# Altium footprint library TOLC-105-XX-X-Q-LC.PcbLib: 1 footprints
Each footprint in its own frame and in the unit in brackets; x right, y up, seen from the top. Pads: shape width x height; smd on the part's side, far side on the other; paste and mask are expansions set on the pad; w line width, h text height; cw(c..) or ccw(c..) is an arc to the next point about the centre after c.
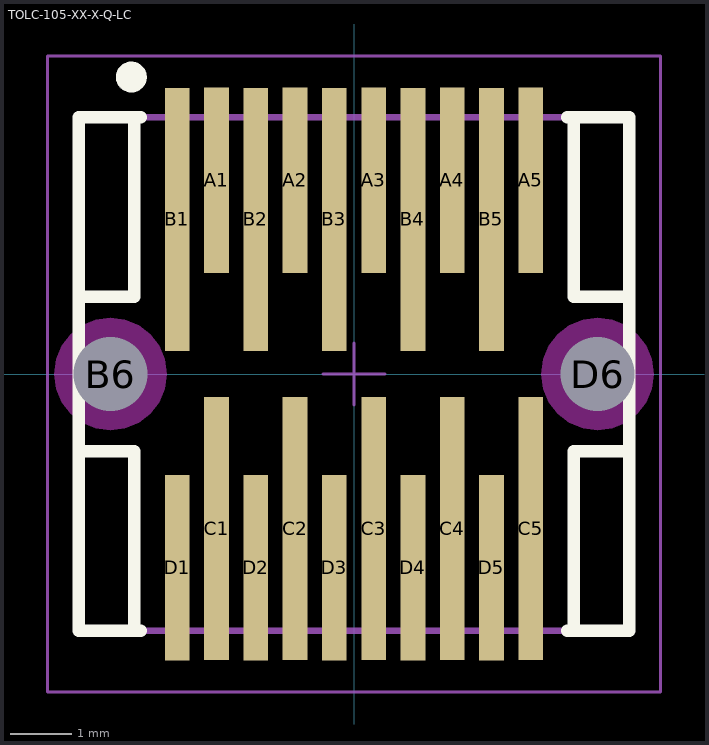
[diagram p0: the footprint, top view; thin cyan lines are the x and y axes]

## TOLC-105-XX-X-Q-LC [mm] "1.27mm pitch, 20 pin, terminal strip; 4 rows, w/locking clips, SMT"
height 5.59
pads (22):
  rect 0.4x3 smd mask+0: A1(-2.222,3.135) A2(-0.953,3.135) A3(0.318,3.135) A4(1.587,3.135) A5(2.857,3.135) D1(-2.857,-3.135) D2(-1.587,-3.135) D3(-0.318,-3.135) D4(0.953,-3.135) D5(2.222,-3.135)
  rect 0.4x4.25 smd mask+0: B1(-2.857,2.5) B2(-1.587,2.5) B3(-0.318,2.5) B4(0.953,2.5) B5(2.222,2.5) C1(-2.222,-2.5) C2(-0.953,-2.5) C3(0.318,-2.5) C4(1.587,-2.5) C5(2.857,-2.5)
  round 1 hole 1.2 unplated mask+0: B6(-3.937,0) D6(3.937,0)
Top Overlay:
  circle w0.25: c-3.6,4.8 r0.125
  lines w0.2: -4.45,-1.25 -3.55,-1.25 -3.55,-4.15 ; -4.45,1.25 -3.55,1.25 -3.55,4.15 ; -3.45,-4.15 -4.45,-4.15 -4.45,4.15 -3.45,4.15 ; 3.45,-4.15 4.45,-4.15 4.45,4.15 3.45,4.15 ; 3.55,-4.15 3.55,-1.25 4.45,-1.25 ; 3.55,4.15 3.55,1.25 4.45,1.25
Keep-Out Layer:
  pour cut-out: -3.029,0 -3.06,0.235 -3.151,0.454 -3.295,0.642 -3.483,0.786 -3.702,0.877 -3.937,0.908 -4.172,0.877 -4.391,0.786 -4.579,0.642 -4.723,0.454 -4.814,0.235 -4.845,0 -4.814,-0.235 -4.723,-0.454 -4.579,-0.642 -4.391,-0.786 -4.172,-0.877 -3.937,-0.908 -3.702,-0.877 -3.483,-0.786 -3.295,-0.642 -3.151,-0.454 -3.06,-0.235
  pour cut-out: 4.845,0 4.814,0.235 4.723,0.454 4.579,0.642 4.391,0.786 4.172,0.877 3.937,0.908 3.702,0.877 3.483,0.786 3.295,0.642 3.151,0.454 3.06,0.235 3.029,0 3.06,-0.235 3.151,-0.454 3.295,-0.642 3.483,-0.786 3.702,-0.877 3.937,-0.908 4.172,-0.877 4.391,-0.786 4.579,-0.642 4.723,-0.454 4.814,-0.235
Mechanical 12:
  lines w0.001: -4.45,-4.15 -4.45,4.15 4.45,4.15 4.45,-4.15 -4.45,-4.15 ; -4.45,-1.25 -3.55,-1.25 -3.55,-4.15 3.55,-4.15 3.55,-1.25 4.45,-1.25 4.45,1.25 3.55,1.25 3.55,4.15 -3.55,4.15 -3.55,1.25 -4.45,1.25 -4.45,-1.25
Mechanical 13:
  circle w0.1: c-2.879,3.349 r0.127
  lines w0.1: -4.45,-4.15 -4.45,4.15 4.45,4.15 4.45,-4.15 -4.45,-4.15 ; -4.45,-1.25 -3.55,-1.25 -3.55,-4.15 3.55,-4.15 3.55,-1.25 4.45,-1.25 4.45,1.25 3.55,1.25 3.55,4.15 -3.55,4.15 -3.55,1.25 -4.45,1.25 -4.45,-1.25
  text ".Designator" at 0,-0.127 h1.52
Mechanical 15:
  lines w0.05: -0.5,0 0.5,0 ; 0,-0.5 0,0.5 ; -4.953,-5.143 4.953,-5.143 4.953,5.143 -4.953,5.143 -4.953,-5.143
